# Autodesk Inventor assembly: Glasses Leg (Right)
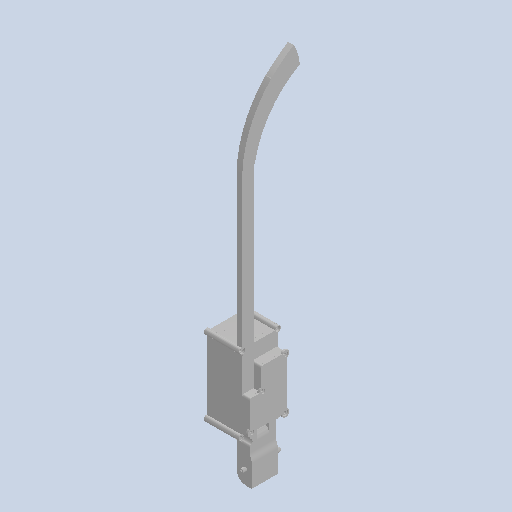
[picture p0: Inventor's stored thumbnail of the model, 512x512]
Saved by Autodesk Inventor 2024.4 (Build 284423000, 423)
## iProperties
Created: 2025-05
Part Number: Glasses Leg (Right)
Document SubType Name: Assembly
Designer: AdminForWorker
Title: Glasses Leg (Right) v38
Author: AdminForWorker
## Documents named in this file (2)
- c:\worker\convert-fusion-r02-cosv3\tmp\job-1\2\temp\files\be827049-a7f2-47ea-a815-8d9efd6bfce9\Glasses Leg (Right) v38.iam
- c:\worker\convert-fusion-r02-cosv3\tmp\job-1\2\temp\files\be827049-a7f2-47ea-a815-8d9efd6bfce9\Right_Leg.iam
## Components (1 placed, 1 different names)
1. Right_Leg:1 [sub-assembly]
